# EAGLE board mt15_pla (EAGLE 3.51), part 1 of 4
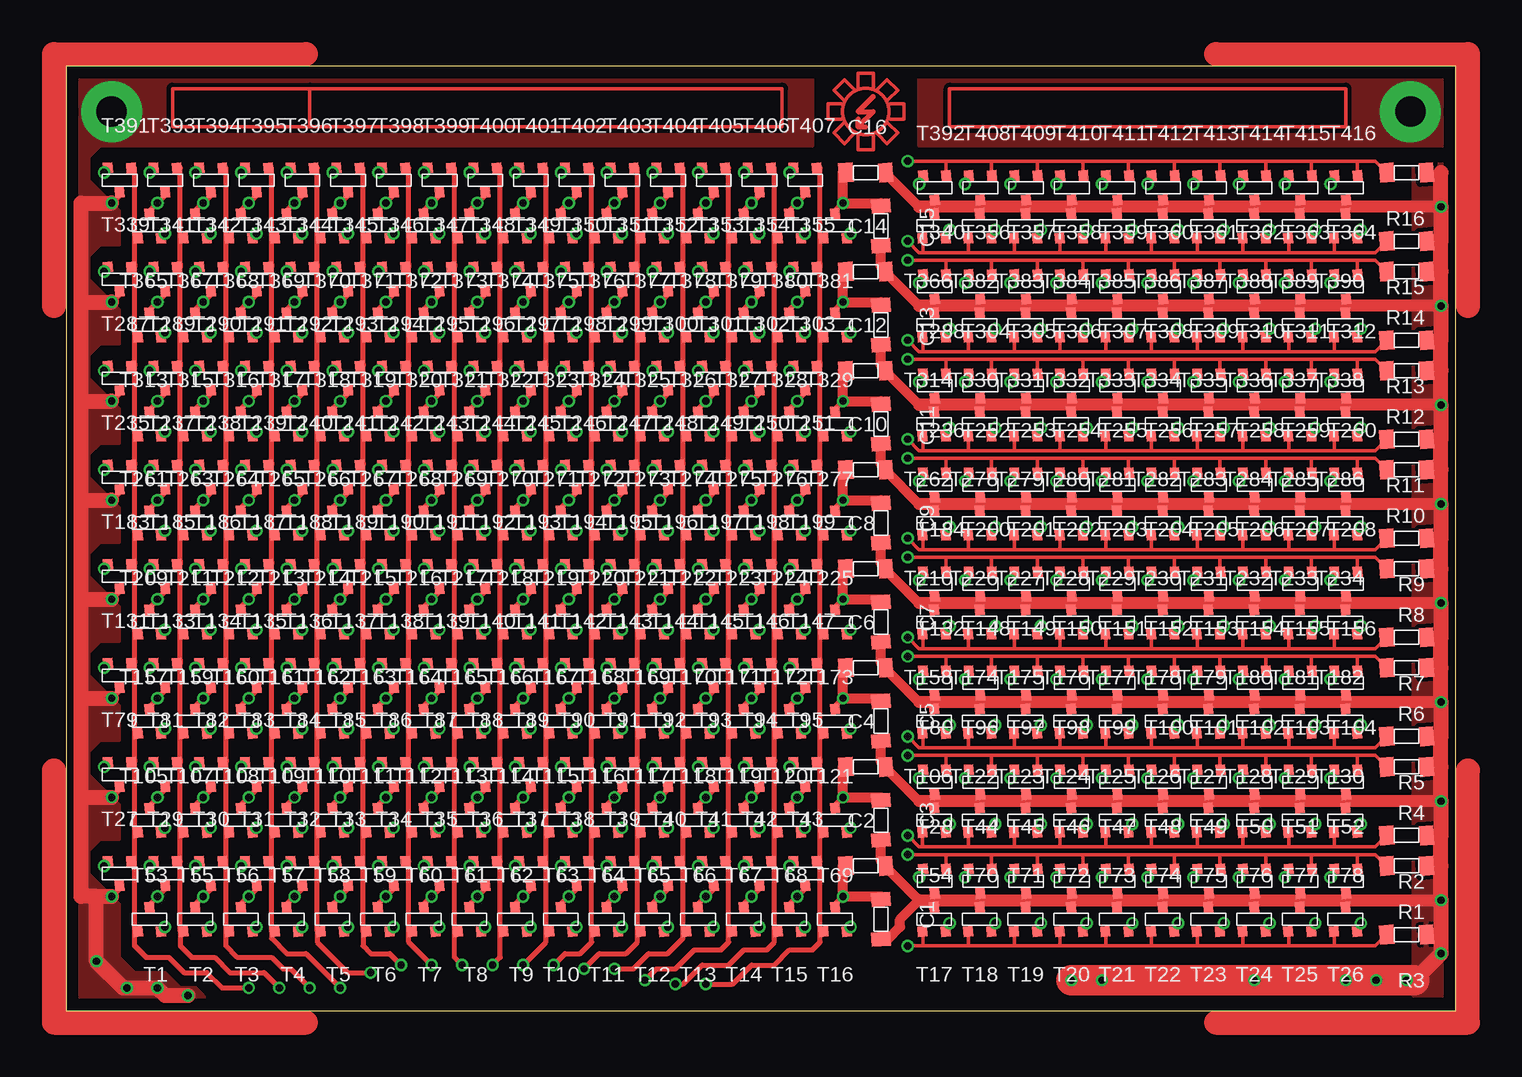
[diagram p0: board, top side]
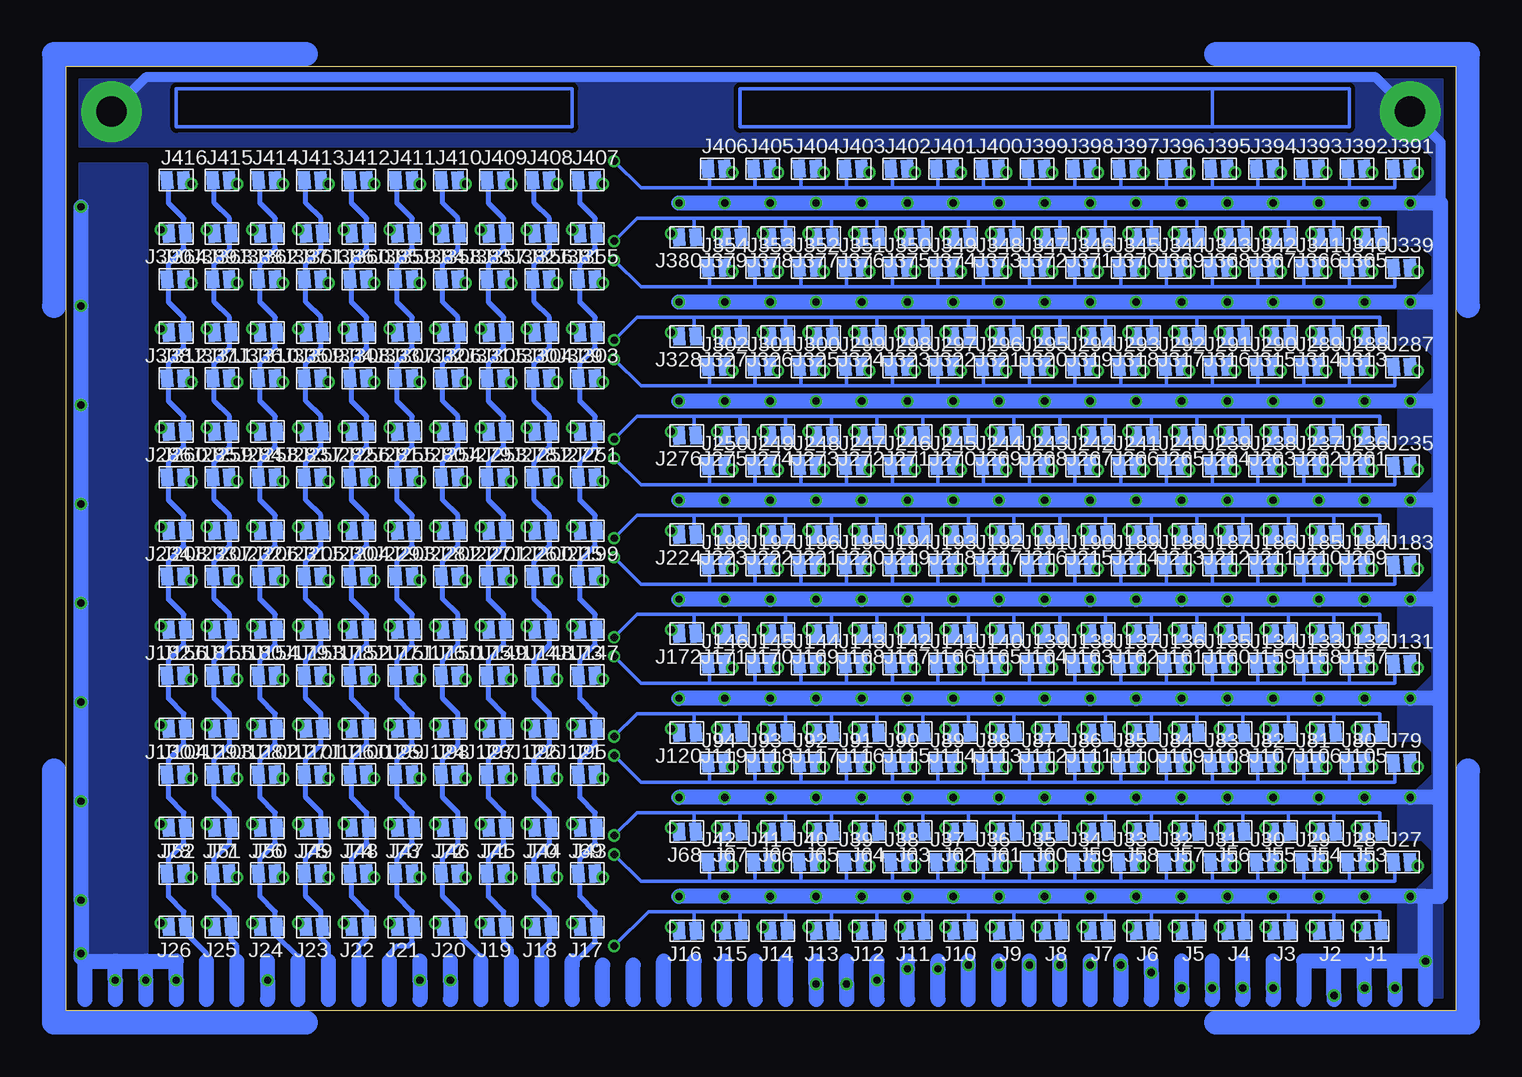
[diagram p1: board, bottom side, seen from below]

Size 115.87 x 78.73 mm. Coordinates in mm from the lower left corner, seen from the top.
Outline: 0,0 115.87,0 115.87,78.73 0,78.73 0,0
Copper layers used: Top, Bottom

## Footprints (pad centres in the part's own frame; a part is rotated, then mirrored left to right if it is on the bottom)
04 = smd 1.194 x 1.6 rotated 4.4:  1.651,0 | smd 1.194 x 1.6 rotated 4.3:  -1.651,0
MPII = smd 1.016 x 1.524 rotated 4.3:  -0.762,0 | smd 1.016 x 1.524 rotated 4.4:  0.635,0
T-23 = smd 0.787 x 0.889 rotated 4.4:  0.991,1.016 | smd 0.787 x 0.889 rotated 4.3:  -0.94,1.016 | smd 0.787 x 0.889 rotated 4.5:  0.025,-1.016

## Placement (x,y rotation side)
C1  100n  [04]  67.94,7.62 270 top
C2  100n  [04]  66.67,12.06 0 top
C3  100n  [04]  67.94,15.88 270 top
C4  100n  [04]  66.67,20.32 0 top
C5  100n  [04]  67.94,24.13 270 top
C6  100n  [04]  66.67,28.57 0 top
C7  100n  [04]  67.94,32.38 270 top
C8  100n  [04]  66.67,36.83 0 top
C9  100n  [04]  67.94,40.64 270 top
C10  100n  [04]  66.67,45.09 0 top
C11  100n  [04]  67.94,48.9 270 top
C12  100n  [04]  66.67,53.34 0 top
C13  100n  [04]  67.94,57.15 270 top
C14  100n  [04]  66.67,61.59 0 top
C15  100n  [04]  67.94,65.41 270 top
C16  100n  [04]  66.67,69.85 0 top
J1  JUMPII  [MPII]  6.99,6.67 180 bottom
J2  JUMPII  [MPII]  10.79,6.67 180 bottom
J3  JUMPII  [MPII]  14.61,6.67 180 bottom
J4  JUMPII  [MPII]  18.41,6.67 180 bottom
J5  JUMPII  [MPII]  22.23,6.67 180 bottom
J6  JUMPII  [MPII]  26.04,6.67 180 bottom
J7  JUMPII  [MPII]  29.84,6.67 180 bottom
J8  JUMPII  [MPII]  33.66,6.67 180 bottom
J9  JUMPII  [MPII]  37.47,6.67 180 bottom
J10  JUMPII  [MPII]  41.27,6.67 180 bottom
J11  JUMPII  [MPII]  45.09,6.67 180 bottom
J12  JUMPII  [MPII]  48.9,6.67 180 bottom
J13  JUMPII  [MPII]  52.7,6.67 180 bottom
J14  JUMPII  [MPII]  56.52,6.67 180 bottom
J15  JUMPII  [MPII]  60.33,6.67 180 bottom
J16  JUMPII  [MPII]  64.14,6.67 180 bottom
J17  JUMPII  [MPII]  72.39,6.99 180 bottom
J18  JUMPII  [MPII]  76.2,6.99 180 bottom
J19  JUMPII  [MPII]  80.01,6.99 180 bottom
J20  JUMPII  [MPII]  83.82,6.99 180 bottom
J21  JUMPII  [MPII]  87.63,6.99 180 bottom
J22  JUMPII  [MPII]  91.44,6.99 180 bottom
J23  JUMPII  [MPII]  95.25,6.99 180 bottom
J24  JUMPII  [MPII]  99.06,6.99 180 bottom
J25  JUMPII  [MPII]  102.87,6.99 180 bottom
J26  JUMPII  [MPII]  106.68,6.99 180 bottom
J27  JUMPII  [MPII]  4.45,12.38 0 bottom
J28  JUMPII  [MPII]  8.26,12.38 0 bottom
J29  JUMPII  [MPII]  12.06,12.38 0 bottom
J30  JUMPII  [MPII]  15.88,12.38 0 bottom
J31  JUMPII  [MPII]  19.68,12.38 0 bottom
J32  JUMPII  [MPII]  23.5,12.38 0 bottom
J33  JUMPII  [MPII]  27.3,12.38 0 bottom
J34  JUMPII  [MPII]  31.11,12.38 0 bottom
J35  JUMPII  [MPII]  34.92,12.38 0 bottom
J36  JUMPII  [MPII]  38.73,12.38 0 bottom
J37  JUMPII  [MPII]  42.55,12.38 0 bottom
J38  JUMPII  [MPII]  46.35,12.38 0 bottom
J39  JUMPII  [MPII]  50.16,12.38 0 bottom
J40  JUMPII  [MPII]  53.98,12.38 0 bottom
J41  JUMPII  [MPII]  57.78,12.38 0 bottom
J42  JUMPII  [MPII]  61.59,12.38 0 bottom
J43  JUMPII  [MPII]  72.39,11.43 0 bottom
J44  JUMPII  [MPII]  76.2,11.43 0 bottom
J45  JUMPII  [MPII]  80.01,11.43 0 bottom
J46  JUMPII  [MPII]  83.82,11.43 0 bottom
J47  JUMPII  [MPII]  87.63,11.43 0 bottom
J48  JUMPII  [MPII]  91.44,11.43 0 bottom
J49  JUMPII  [MPII]  95.25,11.43 0 bottom
J50  JUMPII  [MPII]  99.06,11.43 0 bottom
J51  JUMPII  [MPII]  102.87,11.43 0 bottom
J52  JUMPII  [MPII]  106.68,11.43 0 bottom
J53  JUMPII  [MPII]  6.99,14.92 180 bottom
J54  JUMPII  [MPII]  10.79,14.92 180 bottom
J55  JUMPII  [MPII]  14.61,14.92 180 bottom
J56  JUMPII  [MPII]  18.41,14.92 180 bottom
J57  JUMPII  [MPII]  22.23,14.92 180 bottom
J58  JUMPII  [MPII]  26.04,14.92 180 bottom
J59  JUMPII  [MPII]  29.84,14.92 180 bottom
J60  JUMPII  [MPII]  33.66,14.92 180 bottom
J61  JUMPII  [MPII]  37.47,14.92 180 bottom
J62  JUMPII  [MPII]  41.27,14.92 180 bottom
J63  JUMPII  [MPII]  45.09,14.92 180 bottom
J64  JUMPII  [MPII]  48.9,14.92 180 bottom
J65  JUMPII  [MPII]  52.7,14.92 180 bottom
J66  JUMPII  [MPII]  56.52,14.92 180 bottom
J67  JUMPII  [MPII]  60.33,14.92 180 bottom
J68  JUMPII  [MPII]  64.14,14.92 180 bottom
J69  JUMPII  [MPII]  72.39,15.24 180 bottom
J70  JUMPII  [MPII]  76.2,15.24 180 bottom
J71  JUMPII  [MPII]  80.01,15.24 180 bottom
J72  JUMPII  [MPII]  83.82,15.24 180 bottom
J73  JUMPII  [MPII]  87.63,15.24 180 bottom
J74  JUMPII  [MPII]  91.44,15.24 180 bottom
J75  JUMPII  [MPII]  95.25,15.24 180 bottom
J76  JUMPII  [MPII]  99.06,15.24 180 bottom
J77  JUMPII  [MPII]  102.87,15.24 180 bottom
J78  JUMPII  [MPII]  106.68,15.24 180 bottom
J79  JUMPII  [MPII]  4.45,20.64 0 bottom
J80  JUMPII  [MPII]  8.26,20.64 0 bottom
J81  JUMPII  [MPII]  12.06,20.64 0 bottom
J82  JUMPII  [MPII]  15.88,20.64 0 bottom
J83  JUMPII  [MPII]  19.68,20.64 0 bottom
J84  JUMPII  [MPII]  23.5,20.64 0 bottom
J85  JUMPII  [MPII]  27.3,20.64 0 bottom
J86  JUMPII  [MPII]  31.11,20.64 0 bottom
J87  JUMPII  [MPII]  34.92,20.64 0 bottom
J88  JUMPII  [MPII]  38.73,20.64 0 bottom
J89  JUMPII  [MPII]  42.55,20.64 0 bottom
J90  JUMPII  [MPII]  46.35,20.64 0 bottom
J91  JUMPII  [MPII]  50.16,20.64 0 bottom
J92  JUMPII  [MPII]  53.98,20.64 0 bottom
J93  JUMPII  [MPII]  57.78,20.64 0 bottom
J94  JUMPII  [MPII]  61.59,20.64 0 bottom
J95  JUMPII  [MPII]  72.39,19.68 0 bottom
J96  JUMPII  [MPII]  76.2,19.68 0 bottom
J97  JUMPII  [MPII]  80.01,19.68 0 bottom
J98  JUMPII  [MPII]  83.82,19.68 0 bottom
J99  JUMPII  [MPII]  87.63,19.68 0 bottom
J100  JUMPII  [MPII]  91.44,19.68 0 bottom
J101  JUMPII  [MPII]  95.25,19.68 0 bottom
J102  JUMPII  [MPII]  99.06,19.68 0 bottom
J103  JUMPII  [MPII]  102.87,19.68 0 bottom
J104  JUMPII  [MPII]  106.68,19.68 0 bottom
J105  JUMPII  [MPII]  6.99,23.18 180 bottom
J106  JUMPII  [MPII]  10.79,23.18 180 bottom
J107  JUMPII  [MPII]  14.61,23.18 180 bottom
J108  JUMPII  [MPII]  18.41,23.18 180 bottom
J109  JUMPII  [MPII]  22.23,23.18 180 bottom
J110  JUMPII  [MPII]  26.04,23.18 180 bottom
J111  JUMPII  [MPII]  29.84,23.18 180 bottom
J112  JUMPII  [MPII]  33.66,23.18 180 bottom
J113  JUMPII  [MPII]  37.47,23.18 180 bottom
J114  JUMPII  [MPII]  41.27,23.18 180 bottom
J115  JUMPII  [MPII]  45.09,23.18 180 bottom
J116  JUMPII  [MPII]  48.9,23.18 180 bottom
J117  JUMPII  [MPII]  52.7,23.18 180 bottom
J118  JUMPII  [MPII]  56.52,23.18 180 bottom
J119  JUMPII  [MPII]  60.33,23.18 180 bottom
J120  JUMPII  [MPII]  64.14,23.18 180 bottom
J121  JUMPII  [MPII]  72.39,23.5 180 bottom
J122  JUMPII  [MPII]  76.2,23.5 180 bottom
J123  JUMPII  [MPII]  80.01,23.5 180 bottom
J124  JUMPII  [MPII]  83.82,23.5 180 bottom
J125  JUMPII  [MPII]  87.63,23.5 180 bottom
J126  JUMPII  [MPII]  91.44,23.5 180 bottom
J127  JUMPII  [MPII]  95.25,23.5 180 bottom
J128  JUMPII  [MPII]  99.06,23.5 180 bottom
J129  JUMPII  [MPII]  102.87,23.5 180 bottom
J130  JUMPII  [MPII]  106.68,23.5 180 bottom
J131  JUMPII  [MPII]  4.45,28.89 0 bottom
J132  JUMPII  [MPII]  8.26,28.89 0 bottom
J133  JUMPII  [MPII]  12.06,28.89 0 bottom
J134  JUMPII  [MPII]  15.88,28.89 0 bottom
J135  JUMPII  [MPII]  19.68,28.89 0 bottom
J136  JUMPII  [MPII]  23.5,28.89 0 bottom
J137  JUMPII  [MPII]  27.3,28.89 0 bottom
J138  JUMPII  [MPII]  31.11,28.89 0 bottom
J139  JUMPII  [MPII]  34.92,28.89 0 bottom
J140  JUMPII  [MPII]  38.73,28.89 0 bottom
J141  JUMPII  [MPII]  42.55,28.89 0 bottom
J142  JUMPII  [MPII]  46.35,28.89 0 bottom
J143  JUMPII  [MPII]  50.16,28.89 0 bottom
J144  JUMPII  [MPII]  53.98,28.89 0 bottom
J145  JUMPII  [MPII]  57.78,28.89 0 bottom
J146  JUMPII  [MPII]  61.59,28.89 0 bottom
J147  JUMPII  [MPII]  72.39,27.94 0 bottom
J148  JUMPII  [MPII]  76.2,27.94 0 bottom
J149  JUMPII  [MPII]  80.01,27.94 0 bottom
J150  JUMPII  [MPII]  83.82,27.94 0 bottom
J151  JUMPII  [MPII]  87.63,27.94 0 bottom
J152  JUMPII  [MPII]  91.44,27.94 0 bottom
J153  JUMPII  [MPII]  95.25,27.94 0 bottom
J154  JUMPII  [MPII]  99.06,27.94 0 bottom
J155  JUMPII  [MPII]  102.87,27.94 0 bottom
J156  JUMPII  [MPII]  106.68,27.94 0 bottom
J157  JUMPII  [MPII]  6.99,31.43 180 bottom
J158  JUMPII  [MPII]  10.79,31.43 180 bottom
J159  JUMPII  [MPII]  14.61,31.43 180 bottom
J160  JUMPII  [MPII]  18.41,31.43 180 bottom
J161  JUMPII  [MPII]  22.23,31.43 180 bottom
J162  JUMPII  [MPII]  26.04,31.43 180 bottom
J163  JUMPII  [MPII]  29.84,31.43 180 bottom
J164  JUMPII  [MPII]  33.66,31.43 180 bottom
J165  JUMPII  [MPII]  37.47,31.43 180 bottom
J166  JUMPII  [MPII]  41.27,31.43 180 bottom
J167  JUMPII  [MPII]  45.09,31.43 180 bottom
J168  JUMPII  [MPII]  48.9,31.43 180 bottom
J169  JUMPII  [MPII]  52.7,31.43 180 bottom
J170  JUMPII  [MPII]  56.52,31.43 180 bottom
J171  JUMPII  [MPII]  60.33,31.43 180 bottom
J172  JUMPII  [MPII]  64.14,31.43 180 bottom
J173  JUMPII  [MPII]  72.39,31.75 180 bottom
J174  JUMPII  [MPII]  76.2,31.75 180 bottom
J175  JUMPII  [MPII]  80.01,31.75 180 bottom
J176  JUMPII  [MPII]  83.82,31.75 180 bottom
J177  JUMPII  [MPII]  87.63,31.75 180 bottom
J178  JUMPII  [MPII]  91.44,31.75 180 bottom
J179  JUMPII  [MPII]  95.25,31.75 180 bottom
J180  JUMPII  [MPII]  99.06,31.75 180 bottom
J181  JUMPII  [MPII]  102.87,31.75 180 bottom
J182  JUMPII  [MPII]  106.68,31.75 180 bottom
J183  JUMPII  [MPII]  4.45,37.15 0 bottom
J184  JUMPII  [MPII]  8.26,37.15 0 bottom
J185  JUMPII  [MPII]  12.06,37.15 0 bottom
J186  JUMPII  [MPII]  15.88,37.15 0 bottom
J187  JUMPII  [MPII]  19.68,37.15 0 bottom
J188  JUMPII  [MPII]  23.5,37.15 0 bottom
J189  JUMPII  [MPII]  27.3,37.15 0 bottom
J190  JUMPII  [MPII]  31.11,37.15 0 bottom
J191  JUMPII  [MPII]  34.92,37.15 0 bottom
J192  JUMPII  [MPII]  38.73,37.15 0 bottom
J193  JUMPII  [MPII]  42.55,37.15 0 bottom
J194  JUMPII  [MPII]  46.35,37.15 0 bottom
J195  JUMPII  [MPII]  50.16,37.15 0 bottom
J196  JUMPII  [MPII]  53.98,37.15 0 bottom
J197  JUMPII  [MPII]  57.78,37.15 0 bottom
J198  JUMPII  [MPII]  61.59,37.15 0 bottom
J199  JUMPII  [MPII]  72.39,36.2 0 bottom
J200  JUMPII  [MPII]  76.2,36.2 0 bottom
J201  JUMPII  [MPII]  80.01,36.2 0 bottom
J202  JUMPII  [MPII]  83.82,36.2 0 bottom
J203  JUMPII  [MPII]  87.63,36.2 0 bottom
J204  JUMPII  [MPII]  91.44,36.2 0 bottom
J205  JUMPII  [MPII]  95.25,36.2 0 bottom
J206  JUMPII  [MPII]  99.06,36.2 0 bottom
J207  JUMPII  [MPII]  102.87,36.2 0 bottom
J208  JUMPII  [MPII]  106.68,36.2 0 bottom
J209  JUMPII  [MPII]  6.99,39.69 180 bottom
J210  JUMPII  [MPII]  10.79,39.69 180 bottom
J211  JUMPII  [MPII]  14.61,39.69 180 bottom
J212  JUMPII  [MPII]  18.41,39.69 180 bottom
J213  JUMPII  [MPII]  22.23,39.69 180 bottom
J214  JUMPII  [MPII]  26.04,39.69 180 bottom
J215  JUMPII  [MPII]  29.84,39.69 180 bottom
J216  JUMPII  [MPII]  33.66,39.69 180 bottom
J217  JUMPII  [MPII]  37.47,39.69 180 bottom
J218  JUMPII  [MPII]  41.27,39.69 180 bottom
J219  JUMPII  [MPII]  45.09,39.69 180 bottom
J220  JUMPII  [MPII]  48.9,39.69 180 bottom
J221  JUMPII  [MPII]  52.7,39.69 180 bottom
J222  JUMPII  [MPII]  56.52,39.69 180 bottom
J223  JUMPII  [MPII]  60.33,39.69 180 bottom
J224  JUMPII  [MPII]  64.14,39.69 180 bottom
J225  JUMPII  [MPII]  72.39,40.01 180 bottom
J226  JUMPII  [MPII]  76.2,40.01 180 bottom
J227  JUMPII  [MPII]  80.01,40.01 180 bottom
J228  JUMPII  [MPII]  83.82,40.01 180 bottom
J229  JUMPII  [MPII]  87.63,40.01 180 bottom
J230  JUMPII  [MPII]  91.44,40.01 180 bottom
J231  JUMPII  [MPII]  95.25,40.01 180 bottom
J232  JUMPII  [MPII]  99.06,40.01 180 bottom
J233  JUMPII  [MPII]  102.87,40.01 180 bottom
J234  JUMPII  [MPII]  106.68,40.01 180 bottom
J235  JUMPII  [MPII]  4.45,45.4 0 bottom
J236  JUMPII  [MPII]  8.26,45.4 0 bottom
J237  JUMPII  [MPII]  12.06,45.4 0 bottom
J238  JUMPII  [MPII]  15.88,45.4 0 bottom
J239  JUMPII  [MPII]  19.68,45.4 0 bottom
J240  JUMPII  [MPII]  23.5,45.4 0 bottom
J241  JUMPII  [MPII]  27.3,45.4 0 bottom
J242  JUMPII  [MPII]  31.11,45.4 0 bottom
J243  JUMPII  [MPII]  34.92,45.4 0 bottom
J244  JUMPII  [MPII]  38.73,45.4 0 bottom
J245  JUMPII  [MPII]  42.55,45.4 0 bottom
J246  JUMPII  [MPII]  46.35,45.4 0 bottom
J247  JUMPII  [MPII]  50.16,45.4 0 bottom
J248  JUMPII  [MPII]  53.98,45.4 0 bottom
J249  JUMPII  [MPII]  57.78,45.4 0 bottom
J250  JUMPII  [MPII]  61.59,45.4 0 bottom
J251  JUMPII  [MPII]  72.39,44.45 0 bottom
J252  JUMPII  [MPII]  76.2,44.45 0 bottom
J253  JUMPII  [MPII]  80.01,44.45 0 bottom
J254  JUMPII  [MPII]  83.82,44.45 0 bottom
J255  JUMPII  [MPII]  87.63,44.45 0 bottom
J256  JUMPII  [MPII]  91.44,44.45 0 bottom
J257  JUMPII  [MPII]  95.25,44.45 0 bottom
J258  JUMPII  [MPII]  99.06,44.45 0 bottom
J259  JUMPII  [MPII]  102.87,44.45 0 bottom
J260  JUMPII  [MPII]  106.68,44.45 0 bottom
J261  JUMPII  [MPII]  6.99,47.94 180 bottom
J262  JUMPII  [MPII]  10.79,47.94 180 bottom
J263  JUMPII  [MPII]  14.61,47.94 180 bottom
J264  JUMPII  [MPII]  18.41,47.94 180 bottom
J265  JUMPII  [MPII]  22.23,47.94 180 bottom
J266  JUMPII  [MPII]  26.04,47.94 180 bottom
J267  JUMPII  [MPII]  29.84,47.94 180 bottom
J268  JUMPII  [MPII]  33.66,47.94 180 bottom
J269  JUMPII  [MPII]  37.47,47.94 180 bottom
J270  JUMPII  [MPII]  41.27,47.94 180 bottom
J271  JUMPII  [MPII]  45.09,47.94 180 bottom
J272  JUMPII  [MPII]  48.9,47.94 180 bottom
J273  JUMPII  [MPII]  52.7,47.94 180 bottom
J274  JUMPII  [MPII]  56.52,47.94 180 bottom
J275  JUMPII  [MPII]  60.33,47.94 180 bottom
J276  JUMPII  [MPII]  64.14,47.94 180 bottom
J277  JUMPII  [MPII]  72.39,48.26 180 bottom
J278  JUMPII  [MPII]  76.2,48.26 180 bottom
J279  JUMPII  [MPII]  80.01,48.26 180 bottom
J280  JUMPII  [MPII]  83.82,48.26 180 bottom
J281  JUMPII  [MPII]  87.63,48.26 180 bottom
J282  JUMPII  [MPII]  91.44,48.26 180 bottom
J283  JUMPII  [MPII]  95.25,48.26 180 bottom
J284  JUMPII  [MPII]  99.06,48.26 180 bottom
J285  JUMPII  [MPII]  102.87,48.26 180 bottom
J286  JUMPII  [MPII]  106.68,48.26 180 bottom
J287  JUMPII  [MPII]  4.45,53.66 0 bottom
J288  JUMPII  [MPII]  8.26,53.66 0 bottom
J289  JUMPII  [MPII]  12.06,53.66 0 bottom
J290  JUMPII  [MPII]  15.88,53.66 0 bottom
J291  JUMPII  [MPII]  19.68,53.66 0 bottom
J292  JUMPII  [MPII]  23.5,53.66 0 bottom
J293  JUMPII  [MPII]  27.3,53.66 0 bottom
J294  JUMPII  [MPII]  31.11,53.66 0 bottom
J295  JUMPII  [MPII]  34.92,53.66 0 bottom
J296  JUMPII  [MPII]  38.73,53.66 0 bottom
J297  JUMPII  [MPII]  42.55,53.66 0 bottom
J298  JUMPII  [MPII]  46.35,53.66 0 bottom
J299  JUMPII  [MPII]  50.16,53.66 0 bottom
J300  JUMPII  [MPII]  53.98,53.66 0 bottom
J301  JUMPII  [MPII]  57.78,53.66 0 bottom
J302  JUMPII  [MPII]  61.59,53.66 0 bottom
J303  JUMPII  [MPII]  72.39,52.7 0 bottom
J304  JUMPII  [MPII]  76.2,52.7 0 bottom
J305  JUMPII  [MPII]  80.01,52.7 0 bottom
J306  JUMPII  [MPII]  83.82,52.7 0 bottom
J307  JUMPII  [MPII]  87.63,52.7 0 bottom
J308  JUMPII  [MPII]  91.44,52.7 0 bottom
J309  JUMPII  [MPII]  95.25,52.7 0 bottom
J310  JUMPII  [MPII]  99.06,52.7 0 bottom
J311  JUMPII  [MPII]  102.87,52.7 0 bottom
J312  JUMPII  [MPII]  106.68,52.7 0 bottom
J313  JUMPII  [MPII]  6.99,56.2 180 bottom
J314  JUMPII  [MPII]  10.79,56.2 180 bottom
J315  JUMPII  [MPII]  14.61,56.2 180 bottom
J316  JUMPII  [MPII]  18.41,56.2 180 bottom
J317  JUMPII  [MPII]  22.23,56.2 180 bottom
J318  JUMPII  [MPII]  26.04,56.2 180 bottom
J319  JUMPII  [MPII]  29.84,56.2 180 bottom
J320  JUMPII  [MPII]  33.66,56.2 180 bottom
J321  JUMPII  [MPII]  37.47,56.2 180 bottom
J322  JUMPII  [MPII]  41.27,56.2 180 bottom
J323  JUMPII  [MPII]  45.09,56.2 180 bottom
J324  JUMPII  [MPII]  48.9,56.2 180 bottom
J325  JUMPII  [MPII]  52.7,56.2 180 bottom
J326  JUMPII  [MPII]  56.52,56.2 180 bottom
J327  JUMPII  [MPII]  60.33,56.2 180 bottom
J328  JUMPII  [MPII]  64.14,56.2 180 bottom
J329  JUMPII  [MPII]  72.39,56.52 180 bottom
J330  JUMPII  [MPII]  76.2,56.52 180 bottom
J331  JUMPII  [MPII]  80.01,56.52 180 bottom
J332  JUMPII  [MPII]  83.82,56.52 180 bottom
J333  JUMPII  [MPII]  87.63,56.52 180 bottom
J334  JUMPII  [MPII]  91.44,56.52 180 bottom
J335  JUMPII  [MPII]  95.25,56.52 180 bottom
J336  JUMPII  [MPII]  99.06,56.52 180 bottom
J337  JUMPII  [MPII]  102.87,56.52 180 bottom
J338  JUMPII  [MPII]  106.68,56.52 180 bottom
J339  JUMPII  [MPII]  4.45,61.91 0 bottom
J340  JUMPII  [MPII]  8.26,61.91 0 bottom
J341  JUMPII  [MPII]  12.06,61.91 0 bottom
J342  JUMPII  [MPII]  15.88,61.91 0 bottom
J343  JUMPII  [MPII]  19.68,61.91 0 bottom
J344  JUMPII  [MPII]  23.5,61.91 0 bottom
J345  JUMPII  [MPII]  27.3,61.91 0 bottom
J346  JUMPII  [MPII]  31.11,61.91 0 bottom
J347  JUMPII  [MPII]  34.92,61.91 0 bottom
J348  JUMPII  [MPII]  38.73,61.91 0 bottom
J349  JUMPII  [MPII]  42.55,61.91 0 bottom
J350  JUMPII  [MPII]  46.35,61.91 0 bottom
J351  JUMPII  [MPII]  50.16,61.91 0 bottom
J352  JUMPII  [MPII]  53.98,61.91 0 bottom
J353  JUMPII  [MPII]  57.78,61.91 0 bottom
J354  JUMPII  [MPII]  61.59,61.91 0 bottom
J355  JUMPII  [MPII]  72.39,60.96 0 bottom
J356  JUMPII  [MPII]  76.2,60.96 0 bottom
J357  JUMPII  [MPII]  80.01,60.96 0 bottom
J358  JUMPII  [MPII]  83.82,60.96 0 bottom
J359  JUMPII  [MPII]  87.63,60.96 0 bottom
J360  JUMPII  [MPII]  91.44,60.96 0 bottom
J361  JUMPII  [MPII]  95.25,60.96 0 bottom
J362  JUMPII  [MPII]  99.06,60.96 0 bottom
J363  JUMPII  [MPII]  102.87,60.96 0 bottom
J364  JUMPII  [MPII]  106.68,60.96 0 bottom
J365  JUMPII  [MPII]  6.99,64.45 180 bottom
J366  JUMPII  [MPII]  10.79,64.45 180 bottom
J367  JUMPII  [MPII]  14.61,64.45 180 bottom
J368  JUMPII  [MPII]  18.41,64.45 180 bottom
J369  JUMPII  [MPII]  22.23,64.45 180 bottom
J370  JUMPII  [MPII]  26.04,64.45 180 bottom
J371  JUMPII  [MPII]  29.84,64.45 180 bottom
J372  JUMPII  [MPII]  33.66,64.45 180 bottom
J373  JUMPII  [MPII]  37.47,64.45 180 bottom
J374  JUMPII  [MPII]  41.27,64.45 180 bottom
J375  JUMPII  [MPII]  45.09,64.45 180 bottom
J376  JUMPII  [MPII]  48.9,64.45 180 bottom
J377  JUMPII  [MPII]  52.7,64.45 180 bottom
J378  JUMPII  [MPII]  56.52,64.45 180 bottom
J379  JUMPII  [MPII]  60.33,64.45 180 bottom
J380  JUMPII  [MPII]  64.14,64.45 180 bottom
J381  JUMPII  [MPII]  72.39,64.77 180 bottom
J382  JUMPII  [MPII]  76.2,64.77 180 bottom
J383  JUMPII  [MPII]  80.01,64.77 180 bottom
J384  JUMPII  [MPII]  83.82,64.77 180 bottom
J385  JUMPII  [MPII]  87.63,64.77 180 bottom
J386  JUMPII  [MPII]  91.44,64.77 180 bottom
J387  JUMPII  [MPII]  95.25,64.77 180 bottom
J388  JUMPII  [MPII]  99.06,64.77 180 bottom
J389  JUMPII  [MPII]  102.87,64.77 180 bottom
J390  JUMPII  [MPII]  106.68,64.77 180 bottom
J391  JUMPII  [MPII]  4.45,70.17 0 bottom
J392  JUMPII  [MPII]  8.26,70.17 0 bottom
J393  JUMPII  [MPII]  12.06,70.17 0 bottom
J394  JUMPII  [MPII]  15.88,70.17 0 bottom
J395  JUMPII  [MPII]  19.68,70.17 0 bottom
J396  JUMPII  [MPII]  23.5,70.17 0 bottom
J397  JUMPII  [MPII]  27.3,70.17 0 bottom
J398  JUMPII  [MPII]  31.11,70.17 0 bottom
J399  JUMPII  [MPII]  34.92,70.17 0 bottom
J400  JUMPII  [MPII]  38.73,70.17 0 bottom
J401  JUMPII  [MPII]  42.55,70.17 0 bottom
J402  JUMPII  [MPII]  46.35,70.17 0 bottom
J403  JUMPII  [MPII]  50.16,70.17 0 bottom
J404  JUMPII  [MPII]  53.98,70.17 0 bottom
J405  JUMPII  [MPII]  57.78,70.17 0 bottom
J406  JUMPII  [MPII]  61.59,70.17 0 bottom
J407  JUMPII  [MPII]  72.39,69.22 0 bottom
J408  JUMPII  [MPII]  76.2,69.22 0 bottom
J409  JUMPII  [MPII]  80.01,69.22 0 bottom
J410  JUMPII  [MPII]  83.82,69.22 0 bottom
J411  JUMPII  [MPII]  87.63,69.22 0 bottom
J412  JUMPII  [MPII]  91.44,69.22 0 bottom
J413  JUMPII  [MPII]  95.25,69.22 0 bottom
J414  JUMPII  [MPII]  99.06,69.22 0 bottom
J415  JUMPII  [MPII]  102.87,69.22 0 bottom
J416  JUMPII  [MPII]  106.68,69.22 0 bottom
R1  390  [04]  111.76,12.06 180 top
R2  390  [04]  111.76,14.61 180 top
R3  390  [04]  111.76,6.35 180 top
R4  390  [04]  111.76,20.32 180 top
R5  390  [04]  111.76,22.86 180 top
R6  390  [04]  111.76,28.57 180 top
R7  390  [04]  111.76,31.11 180 top
R8  390  [04]  111.76,36.83 180 top
R9  390  [04]  111.76,39.37 180 top
R10  390  [04]  111.76,45.09 180 top
R11  390  [04]  111.76,47.62 180 top
R12  390  [04]  111.76,53.34 180 top
R13  390  [04]  111.76,55.88 180 top
R14  390  [04]  111.76,61.59 180 top
R15  390  [04]  111.76,64.14 180 top
R16  390  [04]  111.76,69.85 180 top
T1  BC857  [T-23]  6.99,7.62 180 top
T2  BC857  [T-23]  10.79,7.62 180 top
T3  BC857  [T-23]  14.61,7.62 180 top
T4  BC857  [T-23]  18.41,7.62 180 top
T5  BC857  [T-23]  22.23,7.62 180 top
T6  BC857  [T-23]  26.04,7.62 180 top
T7  BC857  [T-23]  29.84,7.62 180 top
T8  BC857  [T-23]  33.66,7.62 180 top
T9  BC857  [T-23]  37.47,7.62 180 top
T10  BC857  [T-23]  41.27,7.62 180 top
T11  BC857  [T-23]  45.09,7.62 180 top
T12  BC857  [T-23]  48.9,7.62 180 top
T13  BC857  [T-23]  52.7,7.62 180 top
T14  BC857  [T-23]  56.52,7.62 180 top
T15  BC857  [T-23]  60.33,7.62 180 top
T16  BC857  [T-23]  64.14,7.62 180 top
T17  BC847  [T-23]  72.39,7.62 180 top
T18  BC847  [T-23]  76.2,7.62 180 top
T19  BC847  [T-23]  80.01,7.62 180 top
T20  BC847  [T-23]  83.82,7.62 180 top
T21  BC847  [T-23]  87.63,7.62 180 top
T22  BC847  [T-23]  91.44,7.62 180 top
T23  BC847  [T-23]  95.25,7.62 180 top
T24  BC847  [T-23]  99.06,7.62 180 top
T25  BC847  [T-23]  102.87,7.62 180 top
T26  BC847  [T-23]  106.68,7.62 180 top
T27  BC857  [T-23]  4.45,11.43 0 top
T28  BC847  [T-23]  72.39,10.79 0 top
T29  BC857  [T-23]  8.26,11.43 0 top
T30  BC857  [T-23]  12.06,11.43 0 top
T31  BC857  [T-23]  15.88,11.43 0 top
T32  BC857  [T-23]  19.68,11.43 0 top
T33  BC857  [T-23]  23.5,11.43 0 top
T34  BC857  [T-23]  27.3,11.43 0 top
T35  BC857  [T-23]  31.11,11.43 0 top
T36  BC857  [T-23]  34.92,11.43 0 top
T37  BC857  [T-23]  38.73,11.43 0 top
T38  BC857  [T-23]  42.55,11.43 0 top
T39  BC857  [T-23]  46.35,11.43 0 top
T40  BC857  [T-23]  50.16,11.43 0 top
T41  BC857  [T-23]  53.98,11.43 0 top
T42  BC857  [T-23]  57.78,11.43 0 top
T43  BC857  [T-23]  61.59,11.43 0 top
T44  BC847  [T-23]  76.2,10.79 0 top
T45  BC847  [T-23]  80.01,10.79 0 top
T46  BC847  [T-23]  83.82,10.79 0 top
T47  BC847  [T-23]  87.63,10.79 0 top
T48  BC847  [T-23]  91.44,10.79 0 top
T49  BC847  [T-23]  95.25,10.79 0 top
T50  BC847  [T-23]  99.06,10.79 0 top
T51  BC847  [T-23]  102.87,10.79 0 top
T52  BC847  [T-23]  106.68,10.79 0 top
T53  BC857  [T-23]  6.99,15.88 180 top
T54  BC847  [T-23]  72.39,15.88 180 top
T55  BC857  [T-23]  10.79,15.88 180 top
T56  BC857  [T-23]  14.61,15.88 180 top
T57  BC857  [T-23]  18.41,15.88 180 top
T58  BC857  [T-23]  22.23,15.88 180 top
T59  BC857  [T-23]  26.04,15.88 180 top
T60  BC857  [T-23]  29.84,15.88 180 top
T61  BC857  [T-23]  33.66,15.88 180 top
T62  BC857  [T-23]  37.47,15.88 180 top
T63  BC857  [T-23]  41.27,15.88 180 top
T64  BC857  [T-23]  45.09,15.88 180 top
T65  BC857  [T-23]  48.9,15.88 180 top
T66  BC857  [T-23]  52.7,15.88 180 top
T67  BC857  [T-23]  56.52,15.88 180 top
T68  BC857  [T-23]  60.33,15.88 180 top
T69  BC857  [T-23]  64.14,15.88 180 top
T70  BC847  [T-23]  76.2,15.88 180 top
T71  BC847  [T-23]  80.01,15.88 180 top
T72  BC847  [T-23]  83.82,15.88 180 top
T73  BC847  [T-23]  87.63,15.88 180 top
T74  BC847  [T-23]  91.44,15.88 180 top
T75  BC847  [T-23]  95.25,15.88 180 top
T76  BC847  [T-23]  99.06,15.88 180 top
T77  BC847  [T-23]  102.87,15.88 180 top
T78  BC847  [T-23]  106.68,15.88 180 top
T79  BC857  [T-23]  4.45,19.68 0 top
T80  BC847  [T-23]  72.39,19.05 0 top
T81  BC857  [T-23]  8.26,19.68 0 top
T82  BC857  [T-23]  12.06,19.68 0 top
T83  BC857  [T-23]  15.88,19.68 0 top
T84  BC857  [T-23]  19.68,19.68 0 top
T85  BC857  [T-23]  23.5,19.68 0 top
T86  BC857  [T-23]  27.3,19.68 0 top
T87  BC857  [T-23]  31.11,19.68 0 top
T88  BC857  [T-23]  34.92,19.68 0 top
T89  BC857  [T-23]  38.73,19.68 0 top
T90  BC857  [T-23]  42.55,19.68 0 top
T91  BC857  [T-23]  46.35,19.68 0 top
T92  BC857  [T-23]  50.16,19.68 0 top
T93  BC857  [T-23]  53.98,19.68 0 top
T94  BC857  [T-23]  57.78,19.68 0 top
T95  BC857  [T-23]  61.59,19.68 0 top
T96  BC847  [T-23]  76.2,19.05 0 top
T97  BC847  [T-23]  80.01,19.05 0 top
T98  BC847  [T-23]  83.82,19.05 0 top
T99  BC847  [T-23]  87.63,19.05 0 top
T100  BC847  [T-23]  91.44,19.05 0 top
T101  BC847  [T-23]  95.25,19.05 0 top
T102  BC847  [T-23]  99.06,19.05 0 top
T103  BC847  [T-23]  102.87,19.05 0 top
T104  BC847  [T-23]  106.68,19.05 0 top
T105  BC857  [T-23]  6.99,24.13 180 top
T106  BC847  [T-23]  72.39,24.13 180 top
T107  BC857  [T-23]  10.79,24.13 180 top
T108  BC857  [T-23]  14.61,24.13 180 top
T109  BC857  [T-23]  18.41,24.13 180 top
T110  BC857  [T-23]  22.23,24.13 180 top
T111  BC857  [T-23]  26.04,24.13 180 top
T112  BC857  [T-23]  29.84,24.13 180 top
T113  BC857  [T-23]  33.66,24.13 180 top
T114  BC857  [T-23]  37.47,24.13 180 top
T115  BC857  [T-23]  41.27,24.13 180 top
T116  BC857  [T-23]  45.09,24.13 180 top
T117  BC857  [T-23]  48.9,24.13 180 top
T118  BC857  [T-23]  52.7,24.13 180 top
T119  BC857  [T-23]  56.52,24.13 180 top
T120  BC857  [T-23]  60.33,24.13 180 top
T121  BC857  [T-23]  64.14,24.13 180 top
T122  BC847  [T-23]  76.2,24.13 180 top
T123  BC847  [T-23]  80.01,24.13 180 top
T124  BC847  [T-23]  83.82,24.13 180 top
T125  BC847  [T-23]  87.63,24.13 180 top
T126  BC847  [T-23]  91.44,24.13 180 top
T127  BC847  [T-23]  95.25,24.13 180 top
T128  BC847  [T-23]  99.06,24.13 180 top
T129  BC847  [T-23]  102.87,24.13 180 top
T130  BC847  [T-23]  106.68,24.13 180 top
T131  BC857  [T-23]  4.45,27.94 0 top
T132  BC847  [T-23]  72.39,27.3 0 top
T133  BC857  [T-23]  8.26,27.94 0 top
T134  BC857  [T-23]  12.06,27.94 0 top
T135  BC857  [T-23]  15.88,27.94 0 top
T136  BC857  [T-23]  19.68,27.94 0 top
T137  BC857  [T-23]  23.5,27.94 0 top
T138  BC857  [T-23]  27.3,27.94 0 top
T139  BC857  [T-23]  31.11,27.94 0 top
T140  BC857  [T-23]  34.92,27.94 0 top
T141  BC857  [T-23]  38.73,27.94 0 top
T142  BC857  [T-23]  42.55,27.94 0 top
T143  BC857  [T-23]  46.35,27.94 0 top
T144  BC857  [T-23]  50.16,27.94 0 top
T145  BC857  [T-23]  53.98,27.94 0 top
T146  BC857  [T-23]  57.78,27.94 0 top
T147  BC857  [T-23]  61.59,27.94 0 top
T148  BC847  [T-23]  76.2,27.3 0 top
T149  BC847  [T-23]  80.01,27.3 0 top
T150  BC847  [T-23]  83.82,27.3 0 top
T151  BC847  [T-23]  87.63,27.3 0 top
T152  BC847  [T-23]  91.44,27.3 0 top
T153  BC847  [T-23]  95.25,27.3 0 top
T154  BC847  [T-23]  99.06,27.3 0 top
T155  BC847  [T-23]  102.87,27.3 0 top
T156  BC847  [T-23]  106.68,27.3 0 top
T157  BC857  [T-23]  6.99,32.38 180 top
T158  BC847  [T-23]  72.39,32.38 180 top
T159  BC857  [T-23]  10.79,32.38 180 top
T160  BC857  [T-23]  14.61,32.38 180 top
T161  BC857  [T-23]  18.41,32.38 180 top
T162  BC857  [T-23]  22.23,32.38 180 top
T163  BC857  [T-23]  26.04,32.38 180 top
T164  BC857  [T-23]  29.84,32.38 180 top
T165  BC857  [T-23]  33.66,32.38 180 top
T166  BC857  [T-23]  37.47,32.38 180 top
T167  BC857  [T-23]  41.27,32.38 180 top
T168  BC857  [T-23]  45.09,32.38 180 top
T169  BC857  [T-23]  48.9,32.38 180 top
T170  BC857  [T-23]  52.7,32.38 180 top
T171  BC857  [T-23]  56.52,32.38 180 top
T172  BC857  [T-23]  60.33,32.38 180 top
T173  BC857  [T-23]  64.14,32.38 180 top
T174  BC847  [T-23]  76.2,32.38 180 top
T175  BC847  [T-23]  80.01,32.38 180 top
T176  BC847  [T-23]  83.82,32.38 180 top
T177  BC847  [T-23]  87.63,32.38 180 top
T178  BC847  [T-23]  91.44,32.38 180 top
T179  BC847  [T-23]  95.25,32.38 180 top
T180  BC847  [T-23]  99.06,32.38 180 top
T181  BC847  [T-23]  102.87,32.38 180 top
T182  BC847  [T-23]  106.68,32.38 180 top
T183  BC857  [T-23]  4.45,36.2 0 top
T184  BC847  [T-23]  72.39,35.56 0 top
T185  BC857  [T-23]  8.26,36.2 0 top
T186  BC857  [T-23]  12.06,36.2 0 top
T187  BC857  [T-23]  15.88,36.2 0 top
T188  BC857  [T-23]  19.68,36.2 0 top
T189  BC857  [T-23]  23.5,36.2 0 top
T190  BC857  [T-23]  27.3,36.2 0 top
T191  BC857  [T-23]  31.11,36.2 0 top
T192  BC857  [T-23]  34.92,36.2 0 top
T193  BC857  [T-23]  38.73,36.2 0 top
T194  BC857  [T-23]  42.55,36.2 0 top
T195  BC857  [T-23]  46.35,36.2 0 top
T196  BC857  [T-23]  50.16,36.2 0 top
T197  BC857  [T-23]  53.98,36.2 0 top
T198  BC857  [T-23]  57.78,36.2 0 top
T199  BC857  [T-23]  61.59,36.2 0 top
T200  BC847  [T-23]  76.2,35.56 0 top
T201  BC847  [T-23]  80.01,35.56 0 top
T202  BC847  [T-23]  83.82,35.56 0 top
T203  BC847  [T-23]  87.63,35.56 0 top
T204  BC847  [T-23]  91.44,35.56 0 top
T205  BC847  [T-23]  95.25,35.56 0 top
T206  BC847  [T-23]  99.06,35.56 0 top
T207  BC847  [T-23]  102.87,35.56 0 top
T208  BC847  [T-23]  106.68,35.56 0 top
T209  BC857  [T-23]  6.99,40.64 180 top
T210  BC847  [T-23]  72.39,40.64 180 top
T211  BC857  [T-23]  10.79,40.64 180 top
T212  BC857  [T-23]  14.61,40.64 180 top
T213  BC857  [T-23]  18.41,40.64 180 top
T214  BC857  [T-23]  22.23,40.64 180 top
T215  BC857  [T-23]  26.04,40.64 180 top
T216  BC857  [T-23]  29.84,40.64 180 top
T217  BC857  [T-23]  33.66,40.64 180 top
T218  BC857  [T-23]  37.47,40.64 180 top
T219  BC857  [T-23]  41.27,40.64 180 top
T220  BC857  [T-23]  45.09,40.64 180 top
T221  BC857  [T-23]  48.9,40.64 180 top
T222  BC857  [T-23]  52.7,40.64 180 top
T223  BC857  [T-23]  56.52,40.64 180 top
T224  BC857  [T-23]  60.33,40.64 180 top
T225  BC857  [T-23]  64.14,40.64 180 top
T226  BC847  [T-23]  76.2,40.64 180 top
T227  BC847  [T-23]  80.01,40.64 180 top
T228  BC847  [T-23]  83.82,40.64 180 top
T229  BC847  [T-23]  87.63,40.64 180 top
T230  BC847  [T-23]  91.44,40.64 180 top
T231  BC847  [T-23]  95.25,40.64 180 top
T232  BC847  [T-23]  99.06,40.64 180 top
T233  BC847  [T-23]  102.87,40.64 180 top
T234  BC847  [T-23]  106.68,40.64 180 top
T235  BC857  [T-23]  4.45,44.45 0 top
T236  BC847  [T-23]  72.39,43.81 0 top
T237  BC857  [T-23]  8.26,44.45 0 top
T238  BC857  [T-23]  12.06,44.45 0 top
T239  BC857  [T-23]  15.88,44.45 0 top
T240  BC857  [T-23]  19.68,44.45 0 top
T241  BC857  [T-23]  23.5,44.45 0 top
T242  BC857  [T-23]  27.3,44.45 0 top
T243  BC857  [T-23]  31.11,44.45 0 top
T244  BC857  [T-23]  34.92,44.45 0 top
T245  BC857  [T-23]  38.73,44.45 0 top
T246  BC857  [T-23]  42.55,44.45 0 top
T247  BC857  [T-23]  46.35,44.45 0 top
T248  BC857  [T-23]  50.16,44.45 0 top
T249  BC857  [T-23]  53.98,44.45 0 top
T250  BC857  [T-23]  57.78,44.45 0 top
T251  BC857  [T-23]  61.59,44.45 0 top
T252  BC847  [T-23]  76.2,43.81 0 top
T253  BC847  [T-23]  80.01,43.81 0 top
T254  BC847  [T-23]  83.82,43.81 0 top
T255  BC847  [T-23]  87.63,43.81 0 top
T256  BC847  [T-23]  91.44,43.81 0 top
T257  BC847  [T-23]  95.25,43.81 0 top
T258  BC847  [T-23]  99.06,43.81 0 top
T259  BC847  [T-23]  102.87,43.81 0 top
T260  BC847  [T-23]  106.68,43.81 0 top
T261  BC857  [T-23]  6.99,48.9 180 top
T262  BC847  [T-23]  72.39,48.9 180 top
T263  BC857  [T-23]  10.79,48.9 180 top
T264  BC857  [T-23]  14.61,48.9 180 top
T265  BC857  [T-23]  18.41,48.9 180 top
T266  BC857  [T-23]  22.23,48.9 180 top
T267  BC857  [T-23]  26.04,48.9 180 top
T268  BC857  [T-23]  29.84,48.9 180 top
T269  BC857  [T-23]  33.66,48.9 180 top
T270  BC857  [T-23]  37.47,48.9 180 top
T271  BC857  [T-23]  41.27,48.9 180 top
T272  BC857  [T-23]  45.09,48.9 180 top
T273  BC857  [T-23]  48.9,48.9 180 top
T274  BC857  [T-23]  52.7,48.9 180 top
T275  BC857  [T-23]  56.52,48.9 180 top
T276  BC857  [T-23]  60.33,48.9 180 top
T277  BC857  [T-23]  64.14,48.9 180 top
T278  BC847  [T-23]  76.2,48.9 180 top
T279  BC847  [T-23]  80.01,48.9 180 top
T280  BC847  [T-23]  83.82,48.9 180 top
T281  BC847  [T-23]  87.63,48.9 180 top
T282  BC847  [T-23]  91.44,48.9 180 top
T283  BC847  [T-23]  95.25,48.9 180 top
T284  BC847  [T-23]  99.06,48.9 180 top
T285  BC847  [T-23]  102.87,48.9 180 top
T286  BC847  [T-23]  106.68,48.9 180 top
T287  BC857  [T-23]  4.45,52.7 0 top
T288  BC847  [T-23]  72.39,52.07 0 top
T289  BC857  [T-23]  8.26,52.7 0 top
T290  BC857  [T-23]  12.06,52.7 0 top
T291  BC857  [T-23]  15.88,52.7 0 top
T292  BC857  [T-23]  19.68,52.7 0 top
T293  BC857  [T-23]  23.5,52.7 0 top
T294  BC857  [T-23]  27.3,52.7 0 top
T295  BC857  [T-23]  31.11,52.7 0 top
T296  BC857  [T-23]  34.92,52.7 0 top
T297  BC857  [T-23]  38.73,52.7 0 top
T298  BC857  [T-23]  42.55,52.7 0 top
T299  BC857  [T-23]  46.35,52.7 0 top
T300  BC857  [T-23]  50.16,52.7 0 top
T301  BC857  [T-23]  53.98,52.7 0 top
T302  BC857  [T-23]  57.78,52.7 0 top
T303  BC857  [T-23]  61.59,52.7 0 top
T304  BC847  [T-23]  76.2,52.07 0 top
T305  BC847  [T-23]  80.01,52.07 0 top
T306  BC847  [T-23]  83.82,52.07 0 top
T307  BC847  [T-23]  87.63,52.07 0 top
T308  BC847  [T-23]  91.44,52.07 0 top
T309  BC847  [T-23]  95.25,52.07 0 top
T310  BC847  [T-23]  99.06,52.07 0 top
T311  BC847  [T-23]  102.87,52.07 0 top
T312  BC847  [T-23]  106.68,52.07 0 top
T313  BC857  [T-23]  6.99,57.15 180 top
T314  BC847  [T-23]  72.39,57.15 180 top
T315  BC857  [T-23]  10.79,57.15 180 top
T316  BC857  [T-23]  14.61,57.15 180 top
T317  BC857  [T-23]  18.41,57.15 180 top
T318  BC857  [T-23]  22.23,57.15 180 top
T319  BC857  [T-23]  26.04,57.15 180 top
T320  BC857  [T-23]  29.84,57.15 180 top
T321  BC857  [T-23]  33.66,57.15 180 top
T322  BC857  [T-23]  37.47,57.15 180 top
T323  BC857  [T-23]  41.27,57.15 180 top
T324  BC857  [T-23]  45.09,57.15 180 top
T325  BC857  [T-23]  48.9,57.15 180 top
T326  BC857  [T-23]  52.7,57.15 180 top
T327  BC857  [T-23]  56.52,57.15 180 top
T328  BC857  [T-23]  60.33,57.15 180 top
T329  BC857  [T-23]  64.14,57.15 180 top
T330  BC847  [T-23]  76.2,57.15 180 top
T331  BC847  [T-23]  80.01,57.15 180 top
T332  BC847  [T-23]  83.82,57.15 180 top
T333  BC847  [T-23]  87.63,57.15 180 top
T334  BC847  [T-23]  91.44,57.15 180 top
T335  BC847  [T-23]  95.25,57.15 180 top
T336  BC847  [T-23]  99.06,57.15 180 top
T337  BC847  [T-23]  102.87,57.15 180 top
T338  BC847  [T-23]  106.68,57.15 180 top
T339  BC857  [T-23]  4.45,60.96 0 top
T340  BC847  [T-23]  72.39,60.33 0 top
T341  BC857  [T-23]  8.26,60.96 0 top
T342  BC857  [T-23]  12.06,60.96 0 top
T343  BC857  [T-23]  15.88,60.96 0 top
T344  BC857  [T-23]  19.68,60.96 0 top
T345  BC857  [T-23]  23.5,60.96 0 top
T346  BC857  [T-23]  27.3,60.96 0 top
T347  BC857  [T-23]  31.11,60.96 0 top
T348  BC857  [T-23]  34.92,60.96 0 top
T349  BC857  [T-23]  38.73,60.96 0 top
T350  BC857  [T-23]  42.55,60.96 0 top
T351  BC857  [T-23]  46.35,60.96 0 top
T352  BC857  [T-23]  50.16,60.96 0 top
T353  BC857  [T-23]  53.98,60.96 0 top
T354  BC857  [T-23]  57.78,60.96 0 top
T355  BC857  [T-23]  61.59,60.96 0 top
T356  BC847  [T-23]  76.2,60.33 0 top
T357  BC847  [T-23]  80.01,60.33 0 top
T358  BC847  [T-23]  83.82,60.33 0 top
T359  BC847  [T-23]  87.63,60.33 0 top
T360  BC847  [T-23]  91.44,60.33 0 top
T361  BC847  [T-23]  95.25,60.33 0 top
T362  BC847  [T-23]  99.06,60.33 0 top
T363  BC847  [T-23]  102.87,60.33 0 top
T364  BC847  [T-23]  106.68,60.33 0 top
T365  BC857  [T-23]  6.99,65.41 180 top
T366  BC847  [T-23]  72.39,65.41 180 top
T367  BC857  [T-23]  10.79,65.41 180 top
T368  BC857  [T-23]  14.61,65.41 180 top
T369  BC857  [T-23]  18.41,65.41 180 top
T370  BC857  [T-23]  22.23,65.41 180 top
T371  BC857  [T-23]  26.04,65.41 180 top
T372  BC857  [T-23]  29.84,65.41 180 top
T373  BC857  [T-23]  33.66,65.41 180 top
T374  BC857  [T-23]  37.47,65.41 180 top
T375  BC857  [T-23]  41.27,65.41 180 top
T376  BC857  [T-23]  45.09,65.41 180 top
T377  BC857  [T-23]  48.9,65.41 180 top
T378  BC857  [T-23]  52.7,65.41 180 top
T379  BC857  [T-23]  56.52,65.41 180 top
T380  BC857  [T-23]  60.33,65.41 180 top
T381  BC857  [T-23]  64.14,65.41 180 top
T382  BC847  [T-23]  76.2,65.41 180 top
T383  BC847  [T-23]  80.01,65.41 180 top
T384  BC847  [T-23]  83.82,65.41 180 top
T385  BC847  [T-23]  87.63,65.41 180 top
T386  BC847  [T-23]  91.44,65.41 180 top
T387  BC847  [T-23]  95.25,65.41 180 top
T388  BC847  [T-23]  99.06,65.41 180 top
T389  BC847  [T-23]  102.87,65.41 180 top
T390  BC847  [T-23]  106.68,65.41 180 top
T391  BC857  [T-23]  4.45,69.22 0 top
T392  BC847  [T-23]  72.39,68.58 0 top
T393  BC857  [T-23]  8.26,69.22 0 top
T394  BC857  [T-23]  12.06,69.22 0 top
T395  BC857  [T-23]  15.88,69.22 0 top
T396  BC857  [T-23]  19.68,69.22 0 top
T397  BC857  [T-23]  23.5,69.22 0 top
T398  BC857  [T-23]  27.3,69.22 0 top
T399  BC857  [T-23]  31.11,69.22 0 top
T400  BC857  [T-23]  34.92,69.22 0 top
T401  BC857  [T-23]  38.73,69.22 0 top
T402  BC857  [T-23]  42.55,69.22 0 top
T403  BC857  [T-23]  46.35,69.22 0 top
T404  BC857  [T-23]  50.16,69.22 0 top
T405  BC857  [T-23]  53.98,69.22 0 top
T406  BC857  [T-23]  57.78,69.22 0 top
T407  BC857  [T-23]  61.59,69.22 0 top
T408  BC847  [T-23]  76.2,68.58 0 top
T409  BC847  [T-23]  80.01,68.58 0 top
T410  BC847  [T-23]  83.82,68.58 0 top
T411  BC847  [T-23]  87.63,68.58 0 top
T412  BC847  [T-23]  91.44,68.58 0 top
T413  BC847  [T-23]  95.25,68.58 0 top
T414  BC847  [T-23]  99.06,68.58 0 top
T415  BC847  [T-23]  102.87,68.58 0 top
T416  BC847  [T-23]  106.68,68.58 0 top
U$41  []  66.67,74.93 0 top

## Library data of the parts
C1-C16 R1-R16 = DISCRETE
J1-J416 = jg
T1-T16 T27 T29-T43 T53 T55-T69 T79 T81-T95 T105 T107-T121 T131 T133-T147 T157 T159-T173 T183 T185-T199 T209 T211-T225 T235 T237-T251 T261 T263-T277 T287 T289-T303 T313 T315-T329 T339 T341-T355 T365 T367-T381 T391 T393-T407 = PNP
T17-T26 T28 T44-T52 T54 T70-T78 T80 T96-T104 T106 T122-T130 T132 T148-T156 T158 T174-T182 T184 T200-T208 T210 T226-T234 T236 T252-T260 T262 T278-T286 T288 T304-T312 T314 T330-T338 T340 T356-T364 T366 T382-T390 T392 T408-T416 = NPN
U$41 = TAF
